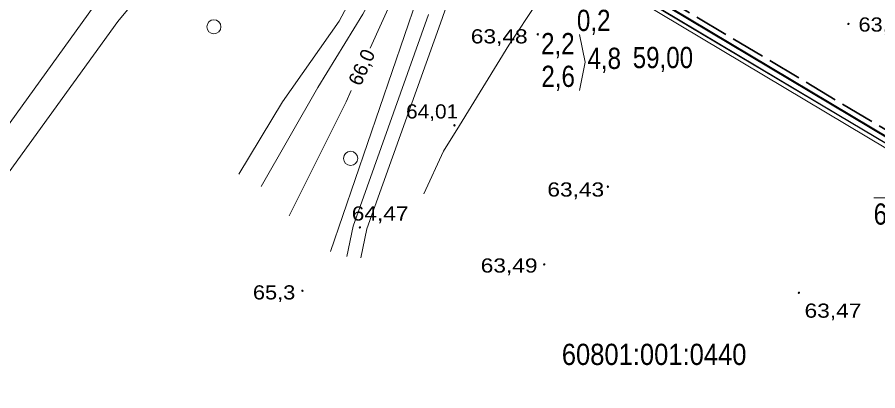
# Model space of a CAD drawing. Extents: x 628176 to 629009, y 6439913 to 6440496.
# Drawn here: x 628239.5 to 628361.2, y 6440112.2 to 6440164.9 of the extents above; entities that cross this region are included whole.
import ezdxf
from ezdxf.enums import TextEntityAlignment as Align

# ---------------------------------------------------------------- set-up
doc = ezdxf.new("R2010")
doc.units = 0
doc.header["$LTSCALE"] = 0.8
doc.linetypes.add('LONG_DASHED', pattern=[7.5, 6, -1.5])
doc.linetypes.add('MEDIUM_DASHED', pattern=[4.5, 3, -1.5])
for name, color, linetype, lineweight in [('1', 7, 'Continuous', 13), ('11', 7, 'Continuous', 13), ('12', 7, 'Continuous', 13), ('14', 7, 'Continuous', 25), ('21', 7, 'MEDIUM_DASHED', 35), ('3', 7, 'Continuous', 13), ('6', 7, 'Continuous', 13)]:
    doc.layers.add(name, color=color, linetype=linetype, lineweight=lineweight)
doc.layers.add('23', color=7, linetype='Continuous')

msp = doc.modelspace()

# ---------------------------------------------------------------- hatches: boundary and pattern name
at = {"layer": '1'}
for points in [[(628357.0999, 6440163.9999, 1), (628356.8999, 6440163.9999, 1)], [(628313.1795, 6440162.5247, 1), (628312.9795, 6440162.5247, 1)], [(628301.4053, 6440149.6641, 1), (628301.2053, 6440149.6641, 1)], [(628323.0999, 6440140.9999, 1), (628322.8999, 6440140.9999, 1)], [(628288.0505, 6440135.2366, 1), (628287.8505, 6440135.2366, 1)], [(628314.0999, 6440129.9999, 1), (628313.8999, 6440129.9999, 1)], [(628279.9142, 6440126.2953, 1), (628279.7142, 6440126.2953, 1)], [(628350.0999, 6440125.9999, 1), (628349.8999, 6440125.9999, 1)]]:
    msp.add_hatch(color=256, dxfattribs=at).paths.add_polyline_path(points)

# ---------------------------------------------------------------- linework, layer by layer
for p, q in [((628299.56, 6440164.78), (628305.08, 6440180.55)), ((628253.73, 6440164.32), (628262.12, 6440174.64)), ((628234.54, 6440144.61), (628250.4, 6440166.54)), ((628286.97, 6440135.42), (628297.64, 6440165.34)), ((628237.77, 6440142.26), (628253.73, 6440164.32)), ((628288.93, 6440135.05), (628299.56, 6440164.78)), ((628286.1, 6440131.13), (628286.97, 6440135.42)), ((628288.08, 6440130.93), (628288.93, 6440135.05))]:
    msp.add_line(p, q, dxfattribs=at)
for centre, radius in [((628267.2987, 6440163.5921), 1), ((628356.9999, 6440163.9999), 0.1), ((628313.0795, 6440162.5247), 0.1), ((628301.3053, 6440149.6641), 0.1), ((628286.6325, 6440144.9925), 1), ((628322.9999, 6440140.9999), 0.1), ((628287.9505, 6440135.2366), 0.1), ((628313.9999, 6440129.9999), 0.1), ((628279.8142, 6440126.2953), 0.1), ((628349.9999, 6440125.9999), 0.1)]:
    msp.add_circle(centre, radius, dxfattribs=at)
at = {"layer": '11'}
msp.add_lwpolyline([(628497.5, 6440118.54), (628474.19, 6440080.39), (628272.25, 6440200.89), (628236.02, 6440221.83), (628393.19, 6440398.39)], dxfattribs=at)
at = {"layer": '12'}
msp.add_line((628360.58, 6440139.43), (628369.45, 6440139.43), dxfattribs=at)
msp.add_lwpolyline([(628318.97, 6440162.5), (628319.79, 6440158.58), (628318.97, 6440154.6)], dxfattribs=at)
at = {"layer": '14'}
msp.add_lwpolyline([(628267.86, 6440203.3), (628311.23, 6440177.63), (628327.53, 6440167.88), (628373.06, 6440140.73), (628474.19, 6440080.39), (628476.16, 6440079.17)], dxfattribs=at)
at = {"layer": '21', "linetype": 'Continuous', "lineweight": 40}
msp.add_lwpolyline([(628496.82, 6440118.96), (628473.92, 6440081.48), (628320.39, 6440173.09)], dxfattribs=at)
at = {"layer": '21', "linetype": 'LONG_DASHED'}
msp.add_lwpolyline([(628496.07, 6440119.27), (628473.65, 6440082.57), (628323.6, 6440172.11)], dxfattribs=at)
at = {"layer": '3'}
for p, q in [((628293, 6440168.58), (628289.4, 6440160.56)), ((628296, 6440167.47), (628283.77, 6440131.85)), ((628309, 6440161), (628302, 6440149.66)), ((628286.71, 6440154.59), (628286, 6440153)), ((628286, 6440153), (628277.95, 6440136.89))]:
    msp.add_line(p, q, dxfattribs=at)
for points in [[(628301, 6440215.43), (628299.8, 6440213), (628299, 6440211), (628298.44, 6440209), (628298.01, 6440207), (628297.6, 6440204), (628296.53, 6440190.04), (628296.24, 6440187.7), (628296, 6440186.33), (628295, 6440181.04), (628294.58, 6440179.51), (628293.46, 6440176), (628291.38, 6440171), (628288.37, 6440165.35), (628282, 6440155), (628274, 6440141)], [(628291, 6440186), (628291, 6440183), (628290.67, 6440179), (628290.19, 6440176), (628289.67, 6440174), (628288.49, 6440171), (628285, 6440164.4), (628277, 6440153), (628270.83, 6440142.75)], [(628320.21, 6440176), (628316, 6440171), (628313, 6440167), (628309, 6440161)], [(628302, 6440149.66), (628299.74, 6440146), (628297, 6440140)]]:
    msp.add_lwpolyline(points, dxfattribs=at)
at = {"layer": '6'}
msp.add_lwpolyline([(628473.77, 6440079.94), (628271.95, 6440200.37), (628235.6, 6440221.38)], dxfattribs=at)

# ---------------------------------------------------------------- texts
at = {"layer": '1'}
for s, width, p in [('63,2', 1.15, (628358.42, 6440162.91)), ('63,48', 1.2, (628303.62, 6440161.24)), ('64,01', 1.1, (628294.47, 6440150.63)), ('63,43', 1.2, (628314.44, 6440139.6)), ('64,47', 1.2, (628286.79, 6440136.21)), ('63,49', 1.2, (628305.02, 6440128.86)), ('65,3', 1.15, (628272.82, 6440125.06)), ('63,47', 1.2, (628350.8, 6440122.48))]:
    msp.add_text(s, height=2, dxfattribs=dict(at, width=width)).set_placement(p)
at = {"layer": '11', "width": 0.85}
msp.add_text('0,2', height=3, dxfattribs=at).set_placement((628320.99, 6440162.99), align=Align.CENTER)
at = {"layer": '12', "width": 0.85}
for s, p in [('2,2', (628315.925, 6440159.71)), ('4,8', (628322.485, 6440157.63)), ('59,00', (628330.775, 6440157.75)), ('2,6', (628315.965, 6440155.09)), ('63,15', (628364.83, 6440135.63))]:
    msp.add_text(s, height=3, dxfattribs=at).set_placement(p, align=Align.CENTER)
at = {"layer": '23', "width": 0.9}
msp.add_text('60801:001:0440', height=3, dxfattribs=at).set_placement((628329.535, 6440115.8), align=Align.CENTER)
at = {"layer": '3'}
msp.add_text('66,0', height=2, rotation=65.807, dxfattribs=at).set_placement((628288.04, 6440155.09))

doc.saveas('drawing.dxf')
